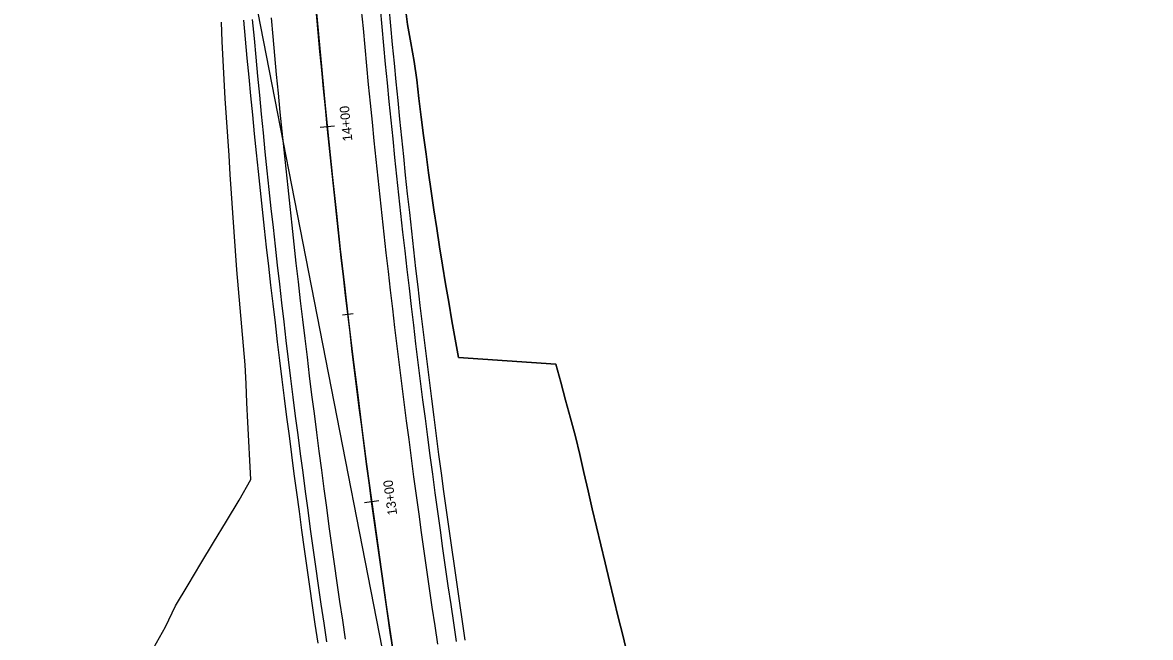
# Model space of a CAD drawing. Extents: x 1150550 to 1151113, y 1141187 to 1143500.
# Drawn here: x 1150657.5 to 1150956.3, y 1142244.5 to 1142407.3 of the extents above; entities that cross this region are included whole.
import ezdxf

# ---------------------------------------------------------------- set-up
doc = ezdxf.new("R2010")
doc.units = 0
for name, color, linetype in [('AC_P', 7, 'Continuous'), ('ACSR_P_T', 7, 'Continuous'), ('ACSRT_P', 7, 'Continuous'), ('Default', 7, 'Continuous'), ('LELB_P', 7, 'Continuous'), ('LFILL_P', 7, 'Continuous'), ('PE_P', 7, 'Continuous'), ('PET_P', 7, 'Continuous'), ('XSCTOP1_P', 7, 'Continuous')]:
    doc.layers.add(name, color=color, linetype=linetype)

msp = doc.modelspace()

# ---------------------------------------------------------------- linework, layer by layer
at = {"layer": 'AC_P'}
msp.add_lwpolyline([(1150755.64, 1142240.87), (1150754.89, 1142245.81), (1150754.16, 1142250.76), (1150753.44, 1142255.71), (1150752.72, 1142260.66), (1150752.02, 1142265.61), (1150751.32, 1142270.56), (1150750.63, 1142275.51), (1150749.95, 1142280.46), (1150749.28, 1142285.42), (1150748.62, 1142290.37), (1150747.97, 1142295.33), (1150747.32, 1142300.29), (1150746.68, 1142305.25), (1150746.06, 1142310.21), (1150745.44, 1142315.17), (1150744.83, 1142320.13), (1150744.23, 1142325.1), (1150743.64, 1142330.06), (1150743.05, 1142335.03), (1150742.48, 1142339.99), (1150741.91, 1142344.96), (1150741.36, 1142349.93), (1150740.81, 1142354.9), (1150740.27, 1142359.87), (1150739.74, 1142364.84), (1150739.22, 1142369.82), (1150738.7, 1142374.79), (1150738.2, 1142379.76), (1150737.7, 1142384.74), (1150737.22, 1142389.72), (1150736.74, 1142394.69), (1150736.27, 1142399.67), (1150735.81, 1142404.65), (1150735.36, 1142409.63)], dxfattribs=at)
msp.add_arc((1153549.06, 1142662.07), 2825, 166.27261, 191.05386, dxfattribs=at)
at = {"layer": 'ACSRT_P'}
for points in [[(1150736.29, 1142379.57), (1150740.11, 1142379.96)], [(1150742.21, 1142329.89), (1150745.07, 1142330.23)], [(1150748.05, 1142280.2), (1150751.85, 1142280.72)]]:
    msp.add_lwpolyline(points, dxfattribs=at)
at = {"layer": 'Default'}
msp.add_line((1150956.27, 1141200.06), (1150657.48, 1142729.55), dxfattribs=at)
at = {"layer": 'LELB_P'}
for points in [[(1150758.81, 1142411.73), (1150759.46, 1142406.81), (1150760.35, 1142401.92), (1150761.25, 1142397.02), (1150761.89, 1142392.11), (1150762.48, 1142387.18), (1150763.09, 1142382.26), (1150763.72, 1142377.35), (1150764.37, 1142372.43), (1150765.04, 1142367.52), (1150765.73, 1142362.61), (1150766.44, 1142357.7), (1150767.19, 1142352.8), (1150767.96, 1142347.9), (1150768.75, 1142343.01), (1150769.55, 1142338.12), (1150770.38, 1142333.23), (1150771.23, 1142328.34), (1150772.1, 1142323.46), (1150772.98, 1142318.58), (1150798.79, 1142316.83), (1150800.06, 1142312.04), (1150801.34, 1142307.26), (1150802.63, 1142302.49), (1150803.95, 1142297.72), (1150805.07, 1142292.92), (1150806.18, 1142288.13), (1150807.28, 1142283.33), (1150808.4, 1142278.54), (1150809.53, 1142273.76), (1150810.66, 1142268.97), (1150811.81, 1142264.19), (1150812.96, 1142259.41), (1150814.12, 1142254.64), (1150815.29, 1142249.86), (1150816.47, 1142245.09), (1150817.6, 1142240.54)], [(1150774.75, 1142243.75), (1150774.02, 1142248.66), (1150773.29, 1142253.57), (1150772.57, 1142258.49), (1150771.86, 1142263.4), (1150771.16, 1142268.32), (1150770.47, 1142273.24), (1150769.78, 1142278.15), (1150769.11, 1142283.07), (1150768.44, 1142287.99), (1150767.78, 1142292.92), (1150767.13, 1142297.84), (1150766.49, 1142302.76), (1150765.86, 1142307.69), (1150765.24, 1142312.62), (1150764.63, 1142317.54), (1150764.02, 1142322.47), (1150763.42, 1142327.4), (1150762.84, 1142332.33), (1150762.26, 1142337.27), (1150761.69, 1142342.2), (1150761.12, 1142347.13), (1150760.57, 1142352.07), (1150760.03, 1142357), (1150759.49, 1142361.94), (1150758.96, 1142366.88), (1150758.45, 1142371.82), (1150757.94, 1142376.76), (1150757.44, 1142381.7), (1150756.94, 1142386.64), (1150756.46, 1142391.58), (1150755.99, 1142396.52), (1150755.52, 1142401.47), (1150755.06, 1142406.41), (1150754.62, 1142411.36)], [(1150692.17, 1142241.64), (1150695.36, 1142247.26), (1150697.98, 1142252.8), (1150701.32, 1142258.42), (1150704.68, 1142264.03), (1150708.07, 1142269.63), (1150711.47, 1142275.22), (1150714.9, 1142280.79), (1150717.96, 1142286.3), (1150717.66, 1142291.36), (1150717.38, 1142296.42), (1150717.14, 1142301.49), (1150716.92, 1142306.55), (1150716.73, 1142311.62), (1150716.48, 1142316.68), (1150716, 1142321.7), (1150715.53, 1142326.73), (1150715.08, 1142331.77), (1150714.67, 1142336.8), (1150714.27, 1142341.84), (1150713.88, 1142346.88), (1150713.51, 1142351.91), (1150713.15, 1142356.95), (1150712.81, 1142361.99), (1150712.48, 1142367.04), (1150712.17, 1142372.08), (1150711.85, 1142377.12), (1150711.5, 1142382.15), (1150711.18, 1142387.19), (1150710.88, 1142392.23), (1150710.62, 1142397.28), (1150710.37, 1142402.32), (1150710.14, 1142407.37)], [(1150735.77, 1142242.96), (1150735.03, 1142247.94), (1150734.31, 1142252.93), (1150733.59, 1142257.91), (1150732.88, 1142262.89), (1150732.17, 1142267.88), (1150731.48, 1142272.86), (1150730.8, 1142277.85), (1150730.12, 1142282.84), (1150729.45, 1142287.83), (1150728.8, 1142292.82), (1150728.15, 1142297.81), (1150727.51, 1142302.81), (1150726.87, 1142307.8), (1150726.25, 1142312.8), (1150725.64, 1142317.79), (1150725.03, 1142322.79), (1150724.44, 1142327.79), (1150723.85, 1142332.79), (1150723.27, 1142337.79), (1150722.7, 1142342.79), (1150722.14, 1142347.79), (1150721.59, 1142352.8), (1150721.05, 1142357.8), (1150720.51, 1142362.81), (1150719.99, 1142367.82), (1150719.47, 1142372.82), (1150718.96, 1142377.83), (1150718.46, 1142382.84), (1150717.97, 1142387.85), (1150717.49, 1142392.86), (1150717.02, 1142397.88), (1150716.56, 1142402.89), (1150716.1, 1142407.9)]]:
    msp.add_lwpolyline(points, dxfattribs=at)
at = {"layer": 'LFILL_P'}
for points in [[(1150817.6, 1142240.54), (1150816.47, 1142245.09), (1150815.29, 1142249.86), (1150814.12, 1142254.64), (1150812.96, 1142259.41), (1150811.81, 1142264.19), (1150810.66, 1142268.97), (1150809.53, 1142273.76), (1150808.4, 1142278.54), (1150807.28, 1142283.33), (1150806.18, 1142288.13), (1150805.07, 1142292.92), (1150803.95, 1142297.72), (1150802.63, 1142302.49), (1150801.34, 1142307.26), (1150800.06, 1142312.04), (1150798.79, 1142316.83), (1150772.98, 1142318.58), (1150772.1, 1142323.46), (1150771.23, 1142328.34), (1150770.38, 1142333.23), (1150769.55, 1142338.12), (1150768.75, 1142343.01), (1150767.96, 1142347.9), (1150767.19, 1142352.8), (1150766.44, 1142357.7), (1150765.73, 1142362.61), (1150765.04, 1142367.52), (1150764.37, 1142372.43), (1150763.72, 1142377.35), (1150763.09, 1142382.26), (1150762.48, 1142387.18), (1150761.89, 1142392.11), (1150761.25, 1142397.02), (1150760.35, 1142401.92), (1150759.46, 1142406.81), (1150758.81, 1142411.73)], [(1150692.17, 1142241.64), (1150695.36, 1142247.26), (1150697.98, 1142252.8), (1150701.32, 1142258.42), (1150704.68, 1142264.03), (1150708.07, 1142269.63), (1150711.47, 1142275.22), (1150714.9, 1142280.79), (1150717.96, 1142286.3), (1150717.66, 1142291.36), (1150717.38, 1142296.42), (1150717.14, 1142301.49), (1150716.92, 1142306.55), (1150716.73, 1142311.62), (1150716.48, 1142316.68), (1150716, 1142321.7), (1150715.53, 1142326.73), (1150715.08, 1142331.77), (1150714.67, 1142336.8), (1150714.27, 1142341.84), (1150713.88, 1142346.88), (1150713.51, 1142351.91), (1150713.15, 1142356.95), (1150712.81, 1142361.99), (1150712.48, 1142367.04), (1150712.17, 1142372.08), (1150711.85, 1142377.12), (1150711.5, 1142382.15), (1150711.18, 1142387.19), (1150710.88, 1142392.23), (1150710.62, 1142397.28), (1150710.37, 1142402.32), (1150710.14, 1142407.37)]]:
    msp.add_lwpolyline(points, dxfattribs=at)
at = {"layer": 'PE_P'}
for points in [[(1150772.45, 1142243.4), (1150771.71, 1142248.32), (1150770.98, 1142253.23), (1150770.26, 1142258.15), (1150769.55, 1142263.07), (1150768.85, 1142267.99), (1150768.16, 1142272.91), (1150767.47, 1142277.84), (1150766.8, 1142282.76), (1150766.13, 1142287.68), (1150765.47, 1142292.61), (1150764.82, 1142297.54), (1150764.18, 1142302.47), (1150763.55, 1142307.4), (1150762.92, 1142312.33), (1150762.31, 1142317.26), (1150761.7, 1142322.19), (1150761.11, 1142327.12), (1150760.52, 1142332.06), (1150759.94, 1142337), (1150759.37, 1142341.93), (1150758.81, 1142346.87), (1150758.25, 1142351.81), (1150757.71, 1142356.75), (1150757.17, 1142361.69), (1150756.64, 1142366.63), (1150756.13, 1142371.57), (1150755.62, 1142376.52), (1150755.11, 1142381.46), (1150754.62, 1142386.41), (1150754.14, 1142391.35), (1150753.66, 1142396.3), (1150753.2, 1142401.25), (1150752.74, 1142406.2), (1150752.29, 1142411.15)], [(1150738.08, 1142243.31), (1150737.34, 1142248.28), (1150736.62, 1142253.26), (1150735.9, 1142258.24), (1150735.19, 1142263.22), (1150734.48, 1142268.2), (1150733.79, 1142273.18), (1150733.11, 1142278.17), (1150732.43, 1142283.15), (1150731.77, 1142288.14), (1150731.11, 1142293.12), (1150730.46, 1142298.11), (1150729.82, 1142303.1), (1150729.19, 1142308.09), (1150728.57, 1142313.08), (1150727.95, 1142318.07), (1150727.35, 1142323.07), (1150726.75, 1142328.06), (1150726.17, 1142333.06), (1150725.59, 1142338.06), (1150725.02, 1142343.05), (1150724.46, 1142348.05), (1150723.91, 1142353.05), (1150723.37, 1142358.05), (1150722.83, 1142363.05), (1150722.31, 1142368.06), (1150721.79, 1142373.06), (1150721.29, 1142378.07), (1150720.79, 1142383.07), (1150720.3, 1142388.08), (1150719.82, 1142393.08), (1150719.35, 1142398.09), (1150718.88, 1142403.1), (1150718.43, 1142408.11)]]:
    msp.add_lwpolyline(points, dxfattribs=at)
at = {"layer": 'PET_P'}
for points in [[(1150743.03, 1142244.05), (1150742.29, 1142249.01), (1150741.56, 1142253.98), (1150740.85, 1142258.95), (1150740.14, 1142263.92), (1150739.44, 1142268.89), (1150738.74, 1142273.87), (1150738.06, 1142278.84), (1150737.39, 1142283.82), (1150736.72, 1142288.79), (1150736.07, 1142293.77), (1150735.42, 1142298.75), (1150734.78, 1142303.73), (1150734.15, 1142308.71), (1150733.53, 1142313.7), (1150732.92, 1142318.68), (1150732.31, 1142323.67), (1150731.72, 1142328.65), (1150731.13, 1142333.64), (1150730.56, 1142338.63), (1150729.99, 1142343.61), (1150729.43, 1142348.6), (1150728.88, 1142353.6), (1150728.34, 1142358.59), (1150727.81, 1142363.58), (1150727.28, 1142368.57), (1150726.77, 1142373.57), (1150726.26, 1142378.56), (1150725.76, 1142383.56), (1150725.27, 1142388.56), (1150724.79, 1142393.56), (1150724.32, 1142398.56), (1150723.86, 1142403.56), (1150723.41, 1142408.56)], [(1150767.5, 1142242.66), (1150766.76, 1142247.58), (1150766.03, 1142252.51), (1150765.31, 1142257.43), (1150764.6, 1142262.36), (1150763.9, 1142267.29), (1150763.2, 1142272.22), (1150762.52, 1142277.15), (1150761.84, 1142282.08), (1150761.17, 1142287.02), (1150760.51, 1142291.95), (1150759.86, 1142296.89), (1150759.22, 1142301.83), (1150758.59, 1142306.76), (1150757.96, 1142311.7), (1150757.35, 1142316.64), (1150756.74, 1142321.59), (1150756.14, 1142326.53), (1150755.55, 1142331.47), (1150754.97, 1142336.42), (1150754.4, 1142341.36), (1150753.84, 1142346.31), (1150753.28, 1142351.26), (1150752.74, 1142356.21), (1150752.2, 1142361.16), (1150751.67, 1142366.11), (1150751.15, 1142371.06), (1150750.64, 1142376.01), (1150750.14, 1142380.96), (1150749.65, 1142385.92), (1150749.16, 1142390.87), (1150748.69, 1142395.83), (1150748.22, 1142400.79), (1150747.76, 1142405.74), (1150747.31, 1142410.7)]]:
    msp.add_lwpolyline(points, dxfattribs=at)
at = {"layer": 'XSCTOP1_P'}
for points in [[(1150743.03, 1142244.05), (1150742.29, 1142249.01), (1150741.56, 1142253.98), (1150740.85, 1142258.95), (1150740.14, 1142263.92), (1150739.44, 1142268.89), (1150738.74, 1142273.87), (1150738.06, 1142278.84), (1150737.39, 1142283.82), (1150736.72, 1142288.79), (1150736.07, 1142293.77), (1150735.42, 1142298.75), (1150734.78, 1142303.73), (1150734.15, 1142308.71), (1150733.53, 1142313.7), (1150732.92, 1142318.68), (1150732.31, 1142323.67), (1150731.72, 1142328.65), (1150731.13, 1142333.64), (1150730.56, 1142338.63), (1150729.99, 1142343.61), (1150729.43, 1142348.6), (1150728.88, 1142353.6), (1150728.34, 1142358.59), (1150727.81, 1142363.58), (1150727.28, 1142368.57), (1150726.77, 1142373.57), (1150726.26, 1142378.56), (1150725.76, 1142383.56), (1150725.27, 1142388.56), (1150724.79, 1142393.56), (1150724.32, 1142398.56), (1150723.86, 1142403.56), (1150723.41, 1142408.56)], [(1150755.64, 1142240.87), (1150754.89, 1142245.81), (1150754.16, 1142250.76), (1150753.44, 1142255.71), (1150752.72, 1142260.66), (1150752.02, 1142265.61), (1150751.32, 1142270.56), (1150750.63, 1142275.51), (1150749.95, 1142280.46), (1150749.28, 1142285.42), (1150748.62, 1142290.37), (1150747.97, 1142295.33), (1150747.32, 1142300.29), (1150746.68, 1142305.25), (1150746.06, 1142310.21), (1150745.44, 1142315.17), (1150744.83, 1142320.13), (1150744.23, 1142325.1), (1150743.64, 1142330.06), (1150743.05, 1142335.03), (1150742.48, 1142339.99), (1150741.91, 1142344.96), (1150741.36, 1142349.93), (1150740.81, 1142354.9), (1150740.27, 1142359.87), (1150739.74, 1142364.84), (1150739.22, 1142369.82), (1150738.7, 1142374.79), (1150738.2, 1142379.76), (1150737.7, 1142384.74), (1150737.22, 1142389.72), (1150736.74, 1142394.69), (1150736.27, 1142399.67), (1150735.81, 1142404.65), (1150735.36, 1142409.63)], [(1150767.5, 1142242.66), (1150766.76, 1142247.58), (1150766.03, 1142252.51), (1150765.31, 1142257.43), (1150764.6, 1142262.36), (1150763.9, 1142267.29), (1150763.2, 1142272.22), (1150762.52, 1142277.15), (1150761.84, 1142282.08), (1150761.17, 1142287.02), (1150760.51, 1142291.95), (1150759.86, 1142296.89), (1150759.22, 1142301.83), (1150758.59, 1142306.76), (1150757.96, 1142311.7), (1150757.35, 1142316.64), (1150756.74, 1142321.59), (1150756.14, 1142326.53), (1150755.55, 1142331.47), (1150754.97, 1142336.42), (1150754.4, 1142341.36), (1150753.84, 1142346.31), (1150753.28, 1142351.26), (1150752.74, 1142356.21), (1150752.2, 1142361.16), (1150751.67, 1142366.11), (1150751.15, 1142371.06), (1150750.64, 1142376.01), (1150750.14, 1142380.96), (1150749.65, 1142385.92), (1150749.16, 1142390.87), (1150748.69, 1142395.83), (1150748.22, 1142400.79), (1150747.76, 1142405.74), (1150747.31, 1142410.7)], [(1150772.45, 1142243.4), (1150771.71, 1142248.32), (1150770.98, 1142253.23), (1150770.26, 1142258.15), (1150769.55, 1142263.07), (1150768.85, 1142267.99), (1150768.16, 1142272.91), (1150767.47, 1142277.84), (1150766.8, 1142282.76), (1150766.13, 1142287.68), (1150765.47, 1142292.61), (1150764.82, 1142297.54), (1150764.18, 1142302.47), (1150763.55, 1142307.4), (1150762.92, 1142312.33), (1150762.31, 1142317.26), (1150761.7, 1142322.19), (1150761.11, 1142327.12), (1150760.52, 1142332.06), (1150759.94, 1142337), (1150759.37, 1142341.93), (1150758.81, 1142346.87), (1150758.25, 1142351.81), (1150757.71, 1142356.75), (1150757.17, 1142361.69), (1150756.64, 1142366.63), (1150756.13, 1142371.57), (1150755.62, 1142376.52), (1150755.11, 1142381.46), (1150754.62, 1142386.41), (1150754.14, 1142391.35), (1150753.66, 1142396.3), (1150753.2, 1142401.25), (1150752.74, 1142406.2), (1150752.29, 1142411.15)], [(1150738.08, 1142243.31), (1150737.34, 1142248.28), (1150736.62, 1142253.26), (1150735.9, 1142258.24), (1150735.19, 1142263.22), (1150734.48, 1142268.2), (1150733.79, 1142273.18), (1150733.11, 1142278.17), (1150732.43, 1142283.15), (1150731.77, 1142288.14), (1150731.11, 1142293.12), (1150730.46, 1142298.11), (1150729.82, 1142303.1), (1150729.19, 1142308.09), (1150728.57, 1142313.08), (1150727.95, 1142318.07), (1150727.35, 1142323.07), (1150726.75, 1142328.06), (1150726.17, 1142333.06), (1150725.59, 1142338.06), (1150725.02, 1142343.05), (1150724.46, 1142348.05), (1150723.91, 1142353.05), (1150723.37, 1142358.05), (1150722.83, 1142363.05), (1150722.31, 1142368.06), (1150721.79, 1142373.06), (1150721.29, 1142378.07), (1150720.79, 1142383.07), (1150720.3, 1142388.08), (1150719.82, 1142393.08), (1150719.35, 1142398.09), (1150718.88, 1142403.1), (1150718.43, 1142408.11)]]:
    msp.add_lwpolyline(points, dxfattribs=at)

# ---------------------------------------------------------------- texts
at = {"layer": 'ACSR_P_T'}
for s, rotation, p in [('14+00', 95.7352, (1150744.86, 1142376)), ('13+00', 97.7634, (1150756.73, 1142276.98))]:
    msp.add_text(s, height=2.501, rotation=rotation, dxfattribs=at).set_placement(p)

doc.saveas('drawing.dxf')
